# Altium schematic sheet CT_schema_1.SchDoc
size 495 x 312 mm
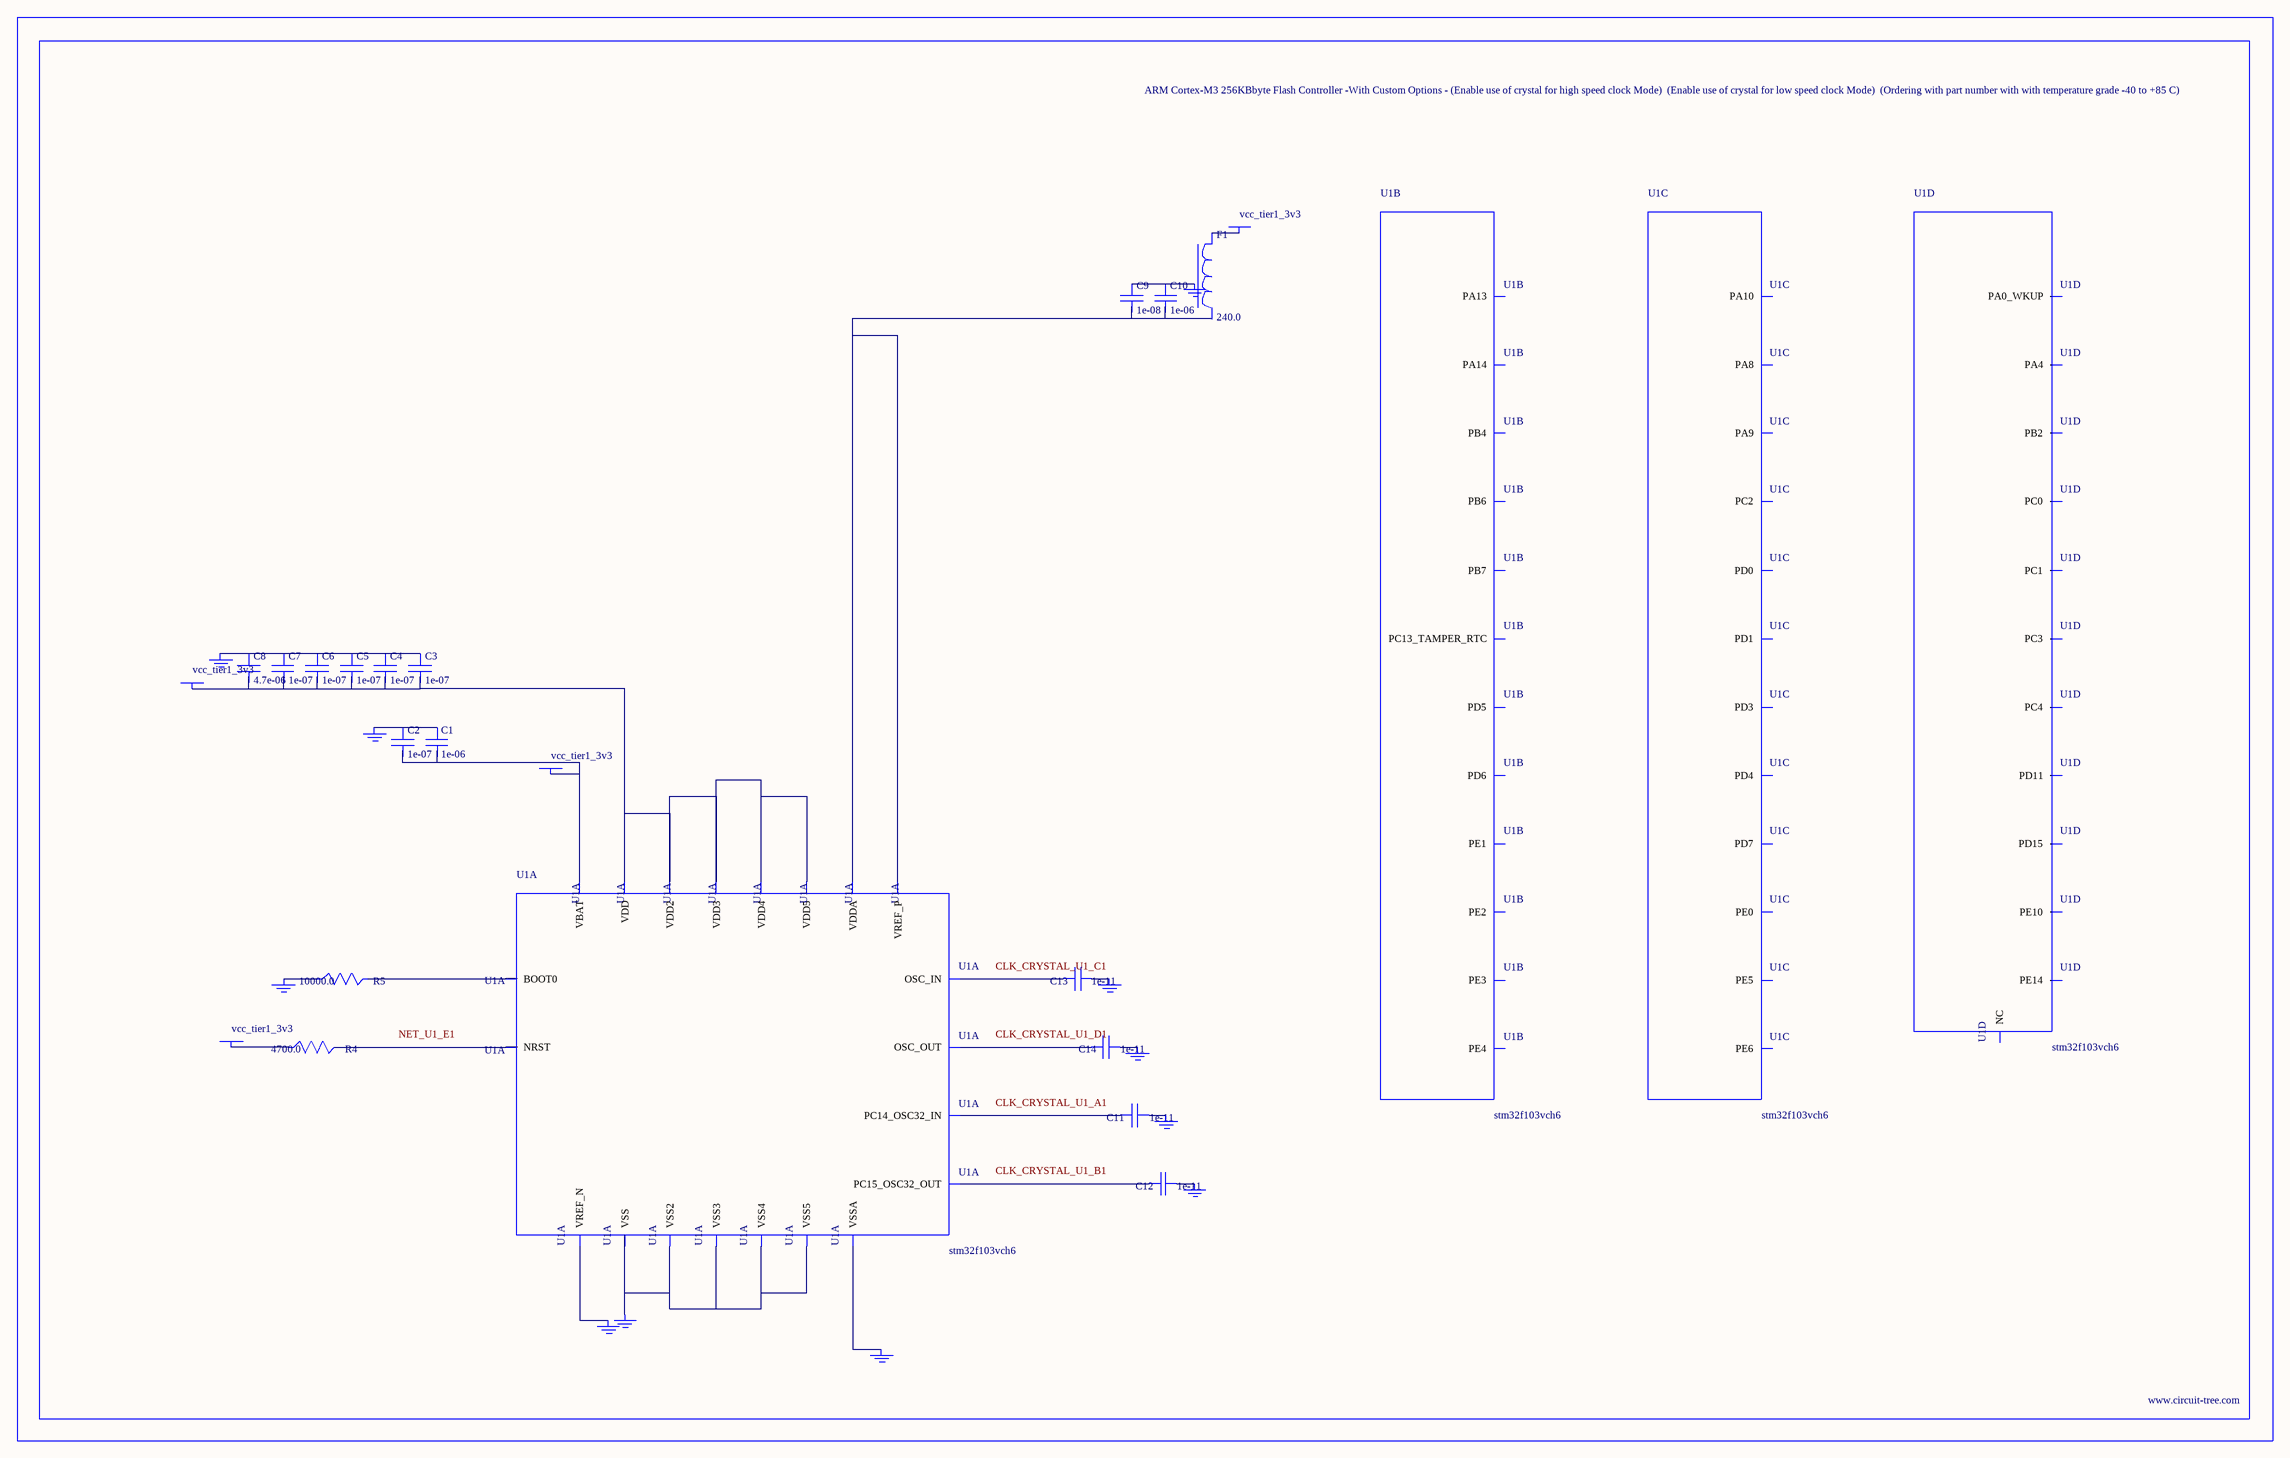
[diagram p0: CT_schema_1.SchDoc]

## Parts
BORDER0  (no value)
C1  1e-06  [C0603]
C2  1e-07  [C0603]
C3  1e-07  [C0603]
C4  1e-07  [C0603]
C5  1e-07  [C0603]
C6  1e-07  [C0603]
C7  1e-07  [C0603]
C8  4.7e-06  [C0603]
C9  1e-08  [C0603]
C10  1e-06  [C0603]
C11  1e-11  [C0402]
C12  1e-11  [C0402]
C13  1e-11  [C0402]
C14  1e-11  [C0402]
F1  240.0  [L0603]
GND_INSTANCE_0_0  (no value)
GND_INSTANCE_0_1  (no value)
GND_INSTANCE_0_2  (no value)
GND_INSTANCE_0_3  (no value)
GND_INSTANCE_0_4  (no value)
GND_INSTANCE_0_5  (no value)
GND_INSTANCE_0_6  (no value)
GND_INSTANCE_0_7  (no value)
GND_INSTANCE_0_8  (no value)
GND_INSTANCE_0_9  (no value)
GND_INSTANCE_0_10  (no value)
POWER_INSTANCE_0_0  vcc_tier1_3v3
POWER_INSTANCE_0_1  vcc_tier1_3v3
POWER_INSTANCE_0_2  vcc_tier1_3v3
POWER_INSTANCE_0_3  vcc_tier1_3v3
R4  4700.0  [R0603]
R5  10000.0  [R0603]
U1  stm32f103vch6  [LFBGA100]  (parts A,B,C,D of 8)

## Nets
NetC1_1: C1.1 C2.1 GND_INSTANCE_0_0.0(GND)
NetC1_2: C1.2 C2.2 POWER_INSTANCE_0_0.0(PWR) U1.B2(VBAT)
NetC3_1: C3.1 C4.1 C5.1 C6.1 C7.1 C8.1 GND_INSTANCE_0_2.0(GND)
NetC3_2: C3.2 C4.2 C5.2 C6.2 C7.2 C8.2 POWER_INSTANCE_0_2.0(PWR) U1.D2(VDD) U1.F4(VDD2) U1.F5(VDD3) U1.F6(VDD4) U1.F7(VDD5)
NetC9_1: C9.1 C10.1 GND_INSTANCE_0_1.0(GND)
NetC9_2: C9.2 C10.2 U1.J1(VREF_P) U1.K1(VDDA)
NetC11_1: C11.1 GND_INSTANCE_0_4.0(GND)
NetC11_2: C11.2 U1.A1(PC14_OSC32_IN)
NetC12_1: C12.1 GND_INSTANCE_0_5.0(GND)
NetC12_2: C12.2 U1.B1(PC15_OSC32_OUT)
NetC13_1: C13.1 GND_INSTANCE_0_6.0(GND)
NetC13_2: C13.2 U1.C1(OSC_IN)
NetC14_1: C14.1 GND_INSTANCE_0_7.0(GND)
NetC14_2: C14.2 U1.D1(OSC_OUT)
NetF1_1: F1.1 POWER_INSTANCE_0_1.0(PWR)
NetGND_INSTANCE_0_3_0: GND_INSTANCE_0_3.0(GND) R5.1
NetGND_INSTANCE_0_8_0: GND_INSTANCE_0_8.0(GND) U1.G1(VSSA)
NetGND_INSTANCE_0_9_0: GND_INSTANCE_0_9.0(GND) U1.H1(VREF_N)
NetGND_INSTANCE_0_10_0: GND_INSTANCE_0_10.0(GND) U1.C2(VSS) U1.E4(VSS2) U1.E5(VSS3) U1.E6(VSS4) U1.E7(VSS5)
NetPOWER_INSTANCE_0_3_0: POWER_INSTANCE_0_3.0(PWR) R4.1
NetR4_2: R4.2 U1.E1(NRST)
NetR5_2: R5.2 U1.D5(BOOT0)

Not connected (* = marked no-connect by the designer): F1 2; U1 A2(PC13_TAMPER_RTC) A3(PE2) A5(PB7) A6(PB4) A9(PA14) A10(PA13) B3(PE3) B5(PB6) B6(PD5) C3(PE4) C4(PE1) C6(PD6) C7(PD3) C9(PA9) D3(PE5) D4(PE0) D6(PD7) D7(PD4) D8(PD0) D9(PA8) D10(PA10) E2(PC2) E3(PE6) E8(PD1) F1(PC0) F2(PC1) F3(PC3) F8(NC) G2(PA0_WKUP) G3(PA4) G4(PC4) G5(PB2) G6(PE10) G7(PE14) G9(PD11) G10(PD15)

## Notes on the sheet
- Labels drawn without touching a wire or pin: CLK_CRYSTAL_U1_A1, CLK_CRYSTAL_U1_B1, CLK_CRYSTAL_U1_C1, CLK_CRYSTAL_U1_D1, NET_U1_E1

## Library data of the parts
BORDER0 = BORDER_PAGE0
C1 C10 = C0603C105K3RACTU
C2-C7 = 06035C104K4Z2A
C8 = GRM188R6YA475KE15D
C9 = 06035C103K4Z2A
C11-C14 = C0402C100K3GACTU
F1 = Z0603C241ASMST
GND_INSTANCE_0_0-GND_INSTANCE_0_10 = GND
POWER_INSTANCE_0_0-POWER_INSTANCE_0_3 = PWR
R4 = RC0603JR-074K7L
R5 = RC0603JR-0710KL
